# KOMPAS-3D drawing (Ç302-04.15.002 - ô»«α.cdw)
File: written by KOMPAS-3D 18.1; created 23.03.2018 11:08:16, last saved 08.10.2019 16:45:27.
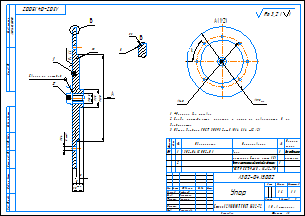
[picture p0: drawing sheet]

Sheet 1: A3, landscape

Document properties: Автор: Милов; Масса: 1.60099; Параметр неуказанной шероховатости: Ra 3,2; Полное имя файла: ..\А302-01.15.002 - Упор.m3d; Организация: Милов

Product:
- Part/product: (unnamed)
  - Component: Болт с шестигранной головкой с фланцем  / ГОСТ Р 55739-М8 x 16-A2-70  | pos. 0  | Раздел спецификации: Детали
  - Component: Упор / (материал Сталь лист 15)  | designation А302-04.15.002-01  | pos. 0  | Раздел спецификации: Детали; Форматы листов документа: БЧ; Примечание: Без отдельного / чертежа

Title block, sheet 1: Наименование: Упор; designation: А302-04.15.002; Материал: Сталь 12Х18Н10Т ГОСТ 5632-72; Масса: 1,6; scale: 1:1; Количество листов документа: 1; organisation: АО «Астерион»; Форматы листов документа: A3; stored path: \\192.168.87.28\Konstructor_doc\Мембранные насосы\Мембранный электропривод\А302-00.00.000 - ASTRA-302 (МЭ200)\Чертежи\А302-00.15.002 - Упор.cdw; Разработал: Лифлянд; Проверил: Борисенко; Т. контр.: Лучихин; Утвердил: Григорьева

Views: Вид 4, Местный разрез 1, Спереди, Вид по стрелке 5, Выносной элемент 6, Вид по стрелке А, Выносной элемент Б, Выносной элемент
Referenced files in D:\Мембранные насосы\Мембранный электропривод\А302-00.00.000 - ASTRA-302 (МЭ200)\3Д ПВХ\: А302-01.15.002 - Упор.a3d, А302-01.15.002 - Упор.m3d
Referenced files in C:\Program Files\ASCON\KOMPAS-3D v18\Libs\PartLib\DATA\VAULT\methods\kompas\3d\: PLib_Bolt_1_ISO_1100.m3d
Referenced files in C:\Program Files\ASCON\KOMPAS-3D V16\Libs\PartLib\DATA\vault\Methods\Kompas\3D\: PLib_Bolt_1_ISO_1100.m3d
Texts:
  Сварка по контуру
  Ra 1,6
  Ra 3,2
  Ra 3,2 ( )
  Болт с шестигранной головкой с фланцем ГОСТ Р 55739-М8 x 16-A2-70
Dimensions and other numbers on the sheet: 13,5; 5,6; 8 отв.; 15; 25; 5; 120; 1; 2; 195; 140; 3; 1:1; 1,6

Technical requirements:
  *Размеры для справок.
  Следы инструмента, царапины и риски на поверхности  В  не
  допускаются.
  Общие допуски ГОСТ 30893.2-mK (H14, h14,  t2/2).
